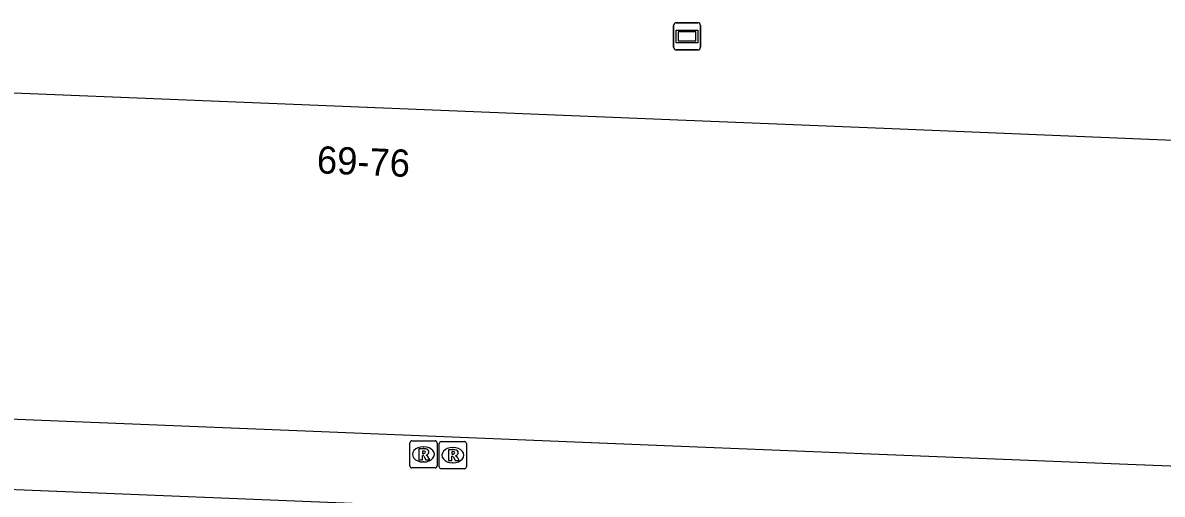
# Model space of a CAD drawing. Extents: x 160891 to 161384, y 386490 to 386907.
# Drawn here: x 161228.09 to 161269.97, y 386816.54 to 386833.87 of the extents above; entities that cross this region are included whole.
import ezdxf

# ---------------------------------------------------------------- set-up
doc = ezdxf.new("R2010")
doc.units = 0
for name, color, linetype in [('IMGEO_Pand', 7, 'Continuous'), ('IMGEO_Pand_nummerreeks', 7, 'Continuous'), ('IMGEO_Reclamebord', 7, 'Continuous'), ('IMGEO_Rijbaan_lokaal_open', 7, 'Continuous'), ('IMGEO_Rioolput', 7, 'Continuous')]:
    doc.layers.add(name, color=color, linetype=linetype)

msp = doc.modelspace()

# ---------------------------------------------------------------- linework, layer by layer
at = {"layer": 'IMGEO_Pand'}
for points in [[(161201.804, 386832.359), (161216.339, 386831.766), (161223.504, 386831.473), (161238.036, 386830.88), (161252.467, 386830.291), (161259.736, 386829.994), (161269.188, 386829.608), (161281.723, 386829.096)], [(161281.723, 386829.096), (161281.256, 386817.22), (161278.605, 386817.352), (161278.601, 386817.252), (161273.381, 386817.451), (161268.706, 386817.64), (161259.254, 386818.021), (161251.986, 386818.314), (161237.554, 386818.897), (161223.022, 386819.483), (161215.857, 386819.772), (161201.32, 386820.359)]]:
    msp.add_lwpolyline(points, dxfattribs=at)
at = {"layer": 'IMGEO_Reclamebord'}
for p, q in [((161252.108, 386833.873), (161252.898, 386833.873)), ((161252.898, 386833.873), (161252.108, 386833.873)), ((161252.008, 386832.973), (161252.008, 386833.773)), ((161252.008, 386833.773), (161252.008, 386832.973)), ((161252.998, 386833.773), (161252.998, 386832.973)), ((161252.998, 386832.973), (161252.998, 386833.773)), ((161252.898, 386832.873), (161252.108, 386832.873)), ((161252.108, 386832.873), (161252.898, 386832.873))]:
    msp.add_line(p, q, dxfattribs=at)
for points in [[(161252.109, 386833.605), (161252.897, 386833.605), (161252.897, 386833.141), (161252.109, 386833.141), (161252.109, 386833.605)], [(161252.174, 386833.54), (161252.174, 386833.206), (161252.832, 386833.206), (161252.832, 386833.54), (161252.174, 386833.54)]]:
    msp.add_lwpolyline(points, dxfattribs=at)
for centre, start, end in [((161252.108, 386833.773), 90, 180), ((161252.108, 386833.773), 90, 180), ((161252.898, 386833.773), 0, 90), ((161252.898, 386833.773), 360, 90), ((161252.108, 386832.973), 180, 270), ((161252.108, 386832.973), 180, 270), ((161252.898, 386832.973), 270, 0), ((161252.898, 386832.973), 270, 0)]:
    msp.add_arc(centre, 0.1, start, end, dxfattribs=at)
at = {"layer": 'IMGEO_Rijbaan_lokaal_open'}
msp.add_lwpolyline([(161201.283, 386817.8), (161267.641, 386815.102)], dxfattribs=at)
at = {"layer": 'IMGEO_Rioolput'}
for p, q in [((161242.313, 386817.582), (161242.313, 386818.434)), ((161242.388, 386818.508), (161243.24, 386818.508)), ((161243.314, 386818.434), (161243.314, 386817.582)), ((161243.395, 386817.555), (161243.395, 386818.407)), ((161243.47, 386818.481), (161244.322, 386818.481)), ((161244.396, 386818.407), (161244.396, 386817.555)), ((161242.801, 386818.288), (161242.826, 386818.288)), ((161243.883, 386818.261), (161243.908, 386818.261)), ((161243.24, 386817.508), (161242.388, 386817.508)), ((161242.824, 386817.728), (161242.799, 386817.728)), ((161243.906, 386817.701), (161243.881, 386817.701)), ((161244.322, 386817.481), (161243.47, 386817.481))]:
    msp.add_line(p, q, dxfattribs=at)
for points in [[(161242.313, 386817.582), (161242.313, 386818.434)], [(161242.388, 386818.508), (161243.24, 386818.508)], [(161243.314, 386818.434), (161243.314, 386817.582)], [(161243.395, 386817.555), (161243.395, 386818.407)], [(161243.47, 386818.481), (161244.322, 386818.481)], [(161244.396, 386818.407), (161244.396, 386817.555)], [(161242.902, 386818.206), (161242.65, 386818.208), (161242.65, 386817.808)], [(161242.65, 386817.808), (161242.774, 386817.808), (161242.774, 386817.97), (161242.785, 386817.97)], [(161242.828, 386818.127), (161242.774, 386818.127), (161242.774, 386818.046)], [(161242.774, 386818.046), (161242.826, 386818.046)], [(161242.832, 386817.941), (161242.903, 386817.808), (161243.043, 386817.808), (161242.978, 386817.934)], [(161243.984, 386818.179), (161243.732, 386818.181), (161243.732, 386817.781)], [(161243.732, 386817.781), (161243.856, 386817.781), (161243.856, 386817.943), (161243.867, 386817.943)], [(161243.91, 386818.1), (161243.856, 386818.1), (161243.856, 386818.019)], [(161243.856, 386818.019), (161243.908, 386818.019)], [(161243.914, 386817.914), (161243.985, 386817.781), (161244.125, 386817.781), (161244.06, 386817.907)], [(161243.24, 386817.508), (161242.388, 386817.508)], [(161244.322, 386817.481), (161243.47, 386817.481)]]:
    msp.add_lwpolyline(points, dxfattribs=at)
for centre, radius, start, end in [((161242.39, 386818.432), 0.0765, 91.552, 178.448), ((161242.39, 386818.432), 0.0765, 91.552, 178.448), ((161243.238, 386818.432), 0.0765, 1.552, 88.448), ((161243.238, 386818.432), 0.0765, 1.552, 88.448), ((161243.472, 386818.405), 0.0765, 91.552, 178.448), ((161243.472, 386818.405), 0.0765, 91.552, 178.448), ((161244.32, 386818.405), 0.0765, 1.552, 88.448), ((161244.32, 386818.405), 0.0765, 1.552, 88.448), ((161242.784, 386817.917), 0.0533, 26.0293, 88.6989), ((161242.81, 386818.235), 0.19, 274.7715, 282.9687), ((161242.834, 386818.031), 0.0964, 77.0061, 93.1865), ((161242.848, 386818.088), 0.0378, 276.6634, 79.6772), ((161242.901, 386818.096), 0.109, 350.3612, 89.416), ((161242.899, 386818.096), 0.112, 277.5842, 350.9817), ((161242.883, 386817.881), 0.108, 29.5134, 73.7905), ((161243.866, 386817.89), 0.0533, 26.0293, 88.6989), ((161243.892, 386818.208), 0.19, 274.7715, 282.9687), ((161243.916, 386818.004), 0.0964, 77.0061, 93.1865), ((161243.93, 386818.061), 0.0378, 276.6634, 79.6772), ((161243.983, 386818.069), 0.109, 350.3612, 89.416), ((161243.981, 386818.069), 0.112, 277.5842, 350.9817), ((161243.965, 386817.854), 0.108, 29.5134, 73.7905), ((161242.39, 386817.584), 0.0765, 181.552, 268.448), ((161242.39, 386817.584), 0.0765, 181.552, 268.448), ((161243.238, 386817.584), 0.0765, 271.552, 358.448), ((161243.238, 386817.584), 0.0765, 271.552, 358.448), ((161243.472, 386817.557), 0.0765, 181.552, 268.448), ((161243.472, 386817.557), 0.0765, 181.552, 268.448), ((161244.32, 386817.557), 0.0765, 271.552, 358.448), ((161244.32, 386817.557), 0.0765, 271.552, 358.448)]:
    msp.add_arc(centre, radius, start, end, dxfattribs=at)
for centre, major_axis, ratio, start_param, end_param in [((161242.8, 386818.008), (-0.387, 0.002), 0.722429, 4.712389, 7.853982), ((161242.825, 386818.008), (-0.39, 0.002), 0.717154, 1.570796, 4.712389), ((161243.882, 386817.981), (-0.387, 0.002), 0.722429, 4.712389, 7.853982), ((161243.907, 386817.981), (-0.39, 0.002), 0.717154, 1.570796, 4.712389)]:
    msp.add_ellipse(centre, major_axis=major_axis, ratio=ratio, start_param=start_param, end_param=end_param, dxfattribs=at)

# ---------------------------------------------------------------- texts
at = {"layer": 'IMGEO_Pand_nummerreeks'}
msp.add_text('69-76', height=1, rotation=357.6628, dxfattribs=at).set_placement((161238.881, 386828.343))

doc.saveas('drawing.dxf')
